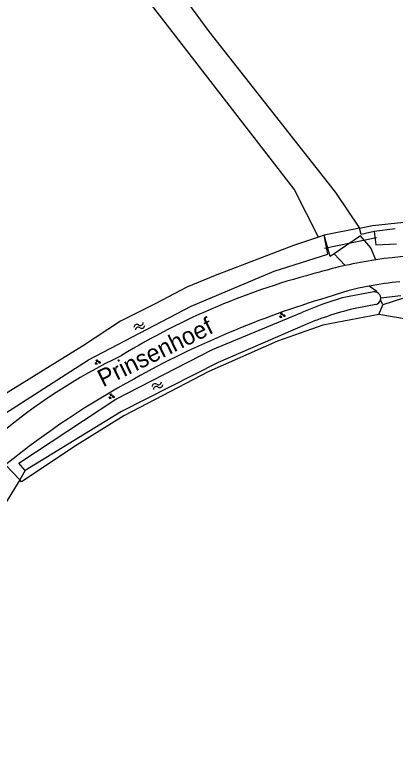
# Model space of a CAD drawing. Extents: x 124000 to 129000, y 395500 to 397503.
# Drawn here: x 125437.3 to 125491.7, y 397039.9 to 397145.1 of the extents above; entities that cross this region are included whole.
import ezdxf

# ---------------------------------------------------------------- set-up
doc = ezdxf.new("R2010")
doc.units = 0
for name, color, linetype in [('gg-afsc-draadraster', 7, 'Continuous'), ('gg-afsc-lijn draadraster', 7, 'Continuous'), ('gg-anno-openbare ruimte label', 7, 'Continuous'), ('gg-knt-bronhoudergrens', 7, 'Continuous'), ('gg-knt-onverhard', 7, 'Continuous'), ('gg-kntw-bovenkant insteek waterloop', 7, 'Continuous'), ('gg-kwrk-duiker nz buis', 7, 'Continuous'), ('gt-grn-groengrens', 7, 'Continuous'), ('gt-grn-weggrens', 7, 'Continuous'), ('gt-symb-groenvak', 7, 'Continuous'), ('gt-symb-watersymbool', 7, 'Continuous'), ('gx-grn-maaiveld', 7, 'Continuous')]:
    doc.layers.add(name, color=color, linetype=linetype)

# ---------------------------------------------------------------- blocks, each defined once
blk = doc.blocks.new('gt0-GRVAK')
at = {"layer": 'gt-symb-groenvak'}
for p, q in [((-0.11, 0.19), (-0.23, 0.24)), ((-0.18, 0.15), (0.09, 0.15)), ((-0.09, 0.21), (-0.16, 0.32)), ((-0.05, 0.21), (-0.05, 0.39)), ((0, 0.21), (0.06, 0.32)), ((0.01, 0.19), (0.13, 0.24)), ((0.26, -0.05), (0.2, 0.06)), ((0.3, -0.05), (0.3, 0.13)), ((0.35, -0.05), (0.41, 0.06)), ((-0.25, -0.23), (-0.36, -0.18)), ((-0.32, -0.26), (-0.05, -0.26)), ((-0.23, -0.21), (-0.29, -0.09)), ((-0.18, -0.2), (-0.18, -0.02)), ((-0.14, -0.21), (-0.07, -0.09)), ((-0.12, -0.23), (0, -0.18)), ((0.24, -0.07), (0.12, -0.02)), ((0.17, -0.11), (0.44, -0.11)), ((0.37, -0.07), (0.49, -0.02))]:
    blk.add_line(p, q, dxfattribs=at)
blk = doc.blocks.new('gt0-WA')
at = {"layer": 'gt-symb-watersymbool'}
for centre, start, end in [((-0.32, 0.02), 28.0725, 151.9275), ((0.43, 0.42), 208.0725, 331.9275), ((-0.32, -0.43), 28.0725, 151.9275), ((0.43, -0.03), 208.0725, 331.9275)]:
    blk.add_arc(centre, 0.425, start, end, dxfattribs=at)

msp = doc.modelspace()

# ---------------------------------------------------------------- linework, layer by layer
at = {"layer": 'gg-afsc-draadraster'}
for p, q in [((125489.04, 397105.43), (125489.1, 397105.3)), ((125492.73, 397104.44), (125489.9, 397103.52)), ((125489.9, 397103.52), (125489.58, 397104.24))]:
    msp.add_line(p, q, dxfattribs=at)
for points in [[(125442.76, 397170.41), (125457.33, 397153.19), (125465.04, 397142.66), (125483.16, 397119.64), (125486.58, 397114.52)], [(125480.7, 397113.22), (125477.25, 397120.08), (125442.98, 397164.48)], [(125486.58, 397114.52), (125488.45, 397114.88), (125492.91, 397115.39), (125498.5, 397115.41), (125502.62, 397115.18), (125505.26, 397114.8), (125510.52, 397113.26), (125512.86, 397112.39), (125515.7, 397111.2), (125519.74, 397109.1), (125523.47, 397106.88), (125561.89, 397080.06), (125567.1, 397077.33), (125570.46, 397075.66), (125574.8, 397074.33), (125578.39, 397074.12), (125581.79, 397074.47), (125587.94, 397077.36), (125600.72, 397084.61), (125616.5, 397094.18), (125624.01, 397098.91)], [(125482.97, 397110.84), (125482.39, 397110.44), (125481.54, 397113.5)], [(125488.18, 397111.68), (125486.72, 397113.43), (125482.97, 397110.84)]]:
    msp.add_lwpolyline(points, dxfattribs=at)
at = {"layer": 'gg-afsc-lijn draadraster'}
for points in [[(125442.76, 397170.41), (125457.33, 397153.19), (125465.04, 397142.66), (125483.16, 397119.64), (125486.58, 397114.52)], [(125480.7, 397113.22), (125477.25, 397120.08), (125442.98, 397164.48)]]:
    msp.add_lwpolyline(points, dxfattribs=at)
at = {"layer": 'gg-knt-bronhoudergrens'}
msp.add_lwpolyline([(125489.35, 397102.15), (125481.34, 397100.63), (125474.84, 397098.36), (125465.02, 397094.01), (125452.89, 397087.66), (125446.22, 397083.51), (125438.26, 397078.2), (125437.98, 397078.49)], dxfattribs=at)
at = {"layer": 'gg-knt-onverhard'}
for p, q in [((125488.9, 397109.99), (125488.18, 397111.68)), ((125482.97, 397110.84), (125484.54, 397109.17)), ((125489.04, 397105.43), (125487.97, 397106.23)), ((125435.95, 397080.62), (125437.98, 397078.49))]:
    msp.add_line(p, q, dxfattribs=at)
for centre, radius, start, end in [((125497.27, 397053.32), 57.28, 98.4058, 102.8398), ((125497.18, 397053.82), 56.78, 79.235, 98.3868), ((125497.31, 397053.36), 57.26, 102.8823, 106.7145), ((125505.96, 397009.03), 102.3, 104.2153, 121.4654), ((125495.82, 397065.2), 41.77, 94.797, 100.8249), ((125495.85, 397064.98), 41.99, 100.8108, 109.4006), ((125521.22, 396973.25), 137.1, 106.6693, 119.171), ((125489.52, 397019.98), 84.78, 115.8408, 130.365), ((125512.96, 396985.45), 122.43, 118.577, 128.9792)]:
    msp.add_arc(centre, radius, start, end, dxfattribs=at)
at = {"layer": 'gg-kntw-bovenkant insteek waterloop'}
for p, q in [((125491.69, 397114.41), (125488.67, 397114.06)), ((125481.54, 397113.5), (125480.7, 397113.22)), ((125488.38, 397105.34), (125484.09, 397104.53)), ((125488.93, 397103.59), (125486.18, 397103.08))]:
    msp.add_line(p, q, dxfattribs=at)
for points in [[(125488.67, 397114.06), (125488.92, 397112.11), (125491.86, 397112.29)], [(125430.94, 397086.54), (125431.8, 397085.4), (125447.8, 397095.66), (125462.51, 397103.34), (125474.35, 397108.37), (125482.05, 397110.8), (125481.54, 397113.5)], [(125480.7, 397113.22), (125477.14, 397112.03), (125465.91, 397107.74), (125461.89, 397106.05), (125457.43, 397103.75), (125452.4, 397101.22), (125446.98, 397097.64), (125434.67, 397090.02), (125431.9, 397087.44)], [(125438.78, 397079.8), (125437.87, 397080.87), (125451.72, 397090.01), (125465.53, 397097.12), (125478.34, 397102.44)], [(125478.8, 397100.69), (125466.36, 397095.29), (125452.54, 397088.27), (125438.78, 397079.8)]]:
    msp.add_lwpolyline(points, dxfattribs=at)
for centre, radius, start, end in [((125488.69, 397104.47), 0.923, 63.681, 109.455), ((125496.11, 397062.5), 43.71, 105.9611, 113.9843), ((125488.69, 397104.48), 0.919, 2.46, 63.49), ((125488.69, 397104.48), 0.917, 344.8479, 2.5166), ((125488.69, 397104.48), 0.919, 285.2702, 344.9071), ((125496.5, 397058.61), 45.65, 103.0611, 112.8092)]:
    msp.add_arc(centre, radius, start, end, dxfattribs=at)
at = {"layer": 'gg-kwrk-duiker nz buis'}
for p, q in [((125481.59, 397111.66), (125489, 397113.17)), ((125489.61, 397104.52), (125492.48, 397104.89))]:
    msp.add_line(p, q, dxfattribs=at)
at = {"layer": 'gt-grn-groengrens'}
for p, q in [((125486.58, 397114.52), (125481.54, 397113.5)), ((125486.79, 397113.61), (125486.58, 397114.52)), ((125488.67, 397114.06), (125486.79, 397113.61)), ((125489.35, 397102.15), (125489.9, 397103.52)), ((125438.78, 397079.8), (125437.98, 397078.49))]:
    msp.add_line(p, q, dxfattribs=at)
at = {"layer": 'gt-grn-weggrens'}
msp.add_line((125437.98, 397078.49), (125435.57, 397074.52), dxfattribs=at)
at = {"layer": 'gx-grn-maaiveld'}
msp.add_lwpolyline([(125583.72, 397061.83), (125586.12, 397058.49), (125590.62, 397054.52), (125731.34, 396972.73), (125734.29, 396973.16), (125739.68, 396969.29), (125747.86, 396963.98), (125766.29, 396952.77), (125851.61, 396902.73), (125849.2, 396899.13), (125736.37, 396965.58), (125723.44, 396972.89), (125652.98, 397014.22), (125582.31, 397055.4), (125575.26, 397057.95), (125562.45, 397063.6), (125549.07, 397071.71), (125532.3, 397083.76), (125522.12, 397090.34), (125513.32, 397095.54), (125505.18, 397099.05), (125501.91, 397100.01), (125489.35, 397102.15)], dxfattribs=at)

# ---------------------------------------------------------------- block references
at = {"layer": 'gt-symb-groenvak'}
for p in [(125475.51, 397102.03), (125449.11, 397095.33), (125451.1, 397090.44)]:
    msp.add_blockref('gt0-GRVAK', p, dxfattribs=at)
at = {"layer": 'gt-symb-watersymbool'}
for p, rotation in [((125455.03, 397100.43), 26.872538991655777), ((125457.62, 397091.95), 27.384970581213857)]:
    msp.add_blockref('gt0-WA', p, dxfattribs=dict(at, rotation=rotation))

# ---------------------------------------------------------------- texts
at = {"layer": 'gg-anno-openbare ruimte label'}
msp.add_text('Prinsenhoef', height=2.5, rotation=26.3, dxfattribs=at).set_placement((125449.9, 397091.7))

doc.saveas('drawing.dxf')
